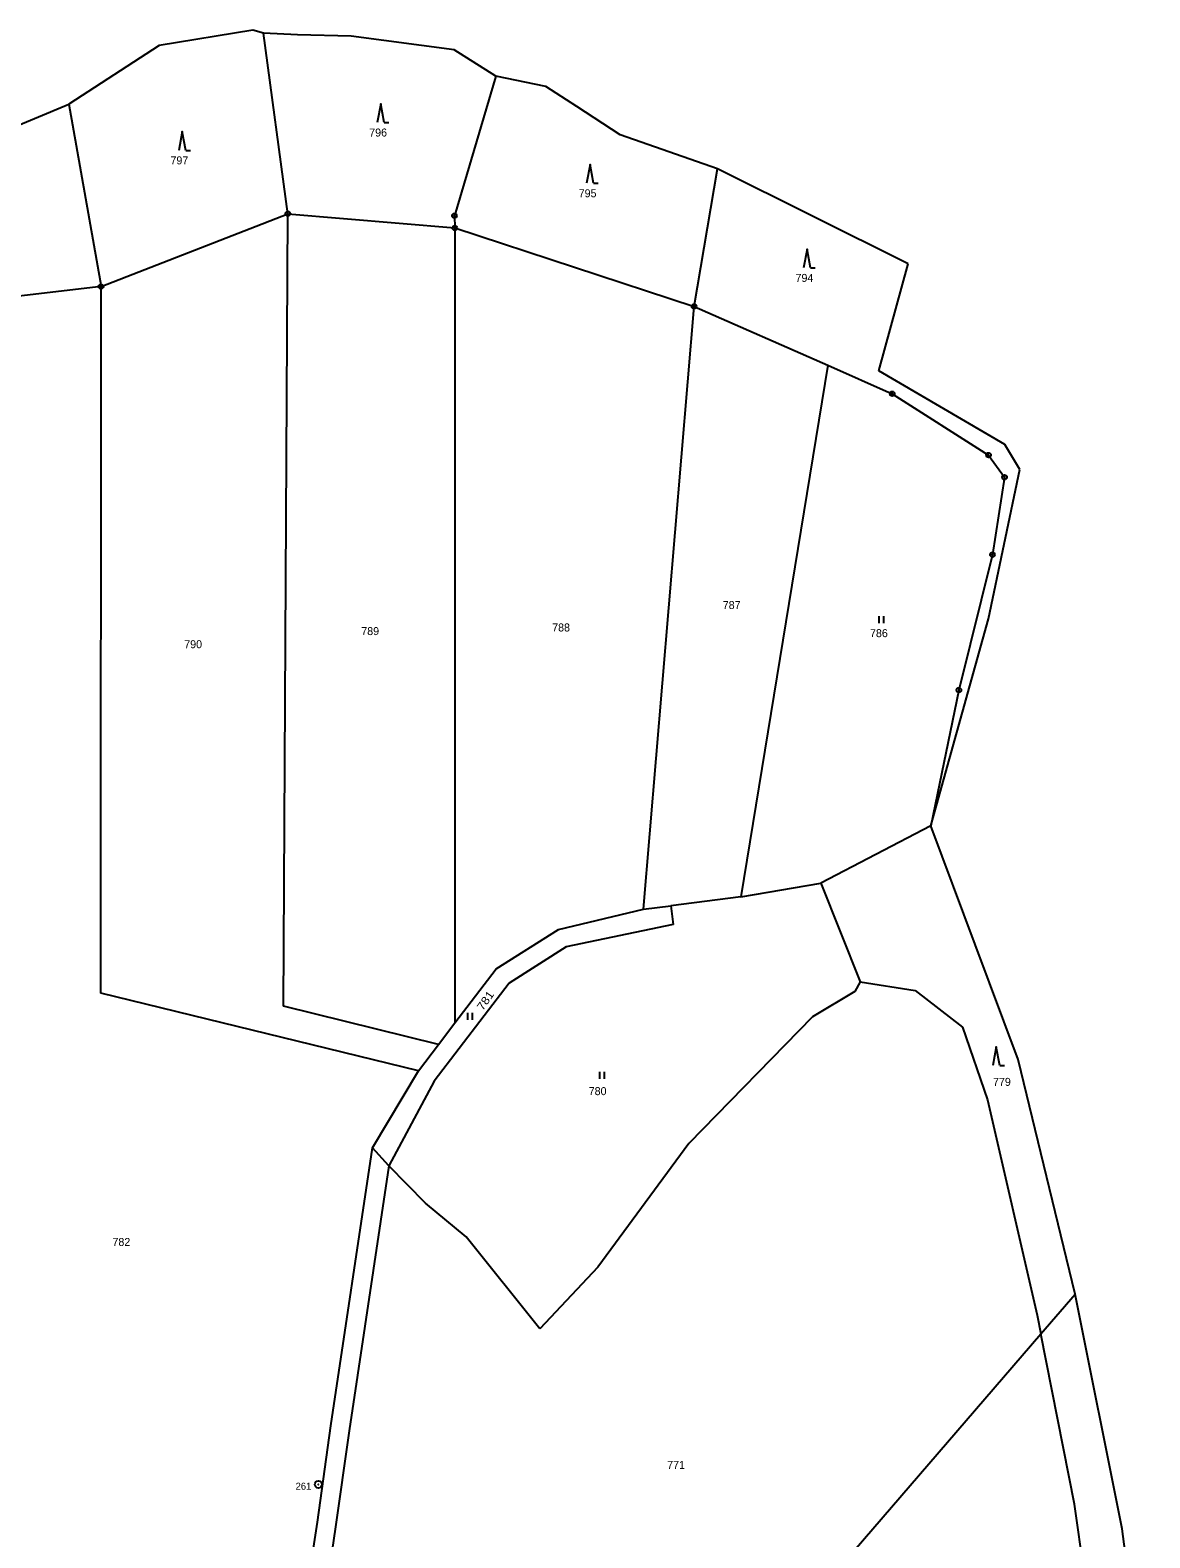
# Model space of a CAD drawing. Extents: x -719614 to -717765, y -1095834 to -1093862.
# Drawn here: x -719008.1 to -718769.8, y -1094182.4 to -1093861.5 of the extents above; entities that cross this region are included whole.
import ezdxf
from ezdxf.enums import TextEntityAlignment as Align

# ---------------------------------------------------------------- set-up
doc = ezdxf.new("R2010")
doc.units = 0
doc.header["$LTSCALE"] = 0.68
for name, color, linetype, lineweight in [('1', 7, 'Continuous', 25), ('3', 7, 'Continuous', 25), ('8', 7, 'Continuous', 25)]:
    doc.layers.add(name, color=color, linetype=linetype, lineweight=lineweight)
doc.layers.add('2', color=7, linetype='Continuous')

msp = doc.modelspace()

# ---------------------------------------------------------------- linework, layer by layer
at = {"layer": '1'}
for p, q in [((-718960.69, -1093861.54), (-718980.62, -1093864.8)), ((-718958.46, -1093862.15), (-718960.69, -1093861.54)), ((-718953.27, -1093900.59), (-718958.46, -1093862.15)), ((-718917.86, -1093865.71), (-718939.76, -1093862.79)), ((-718980.62, -1093864.8), (-718999.88, -1093877.31)), ((-718909.01, -1093871.3), (-718917.86, -1093865.71)), ((-718909.01, -1093871.3), (-718917.82, -1093901.03)), ((-718898.35, -1093873.52), (-718909.01, -1093871.3)), ((-718891.76, -1093877.82), (-718898.35, -1093873.52)), ((-719037.22, -1093892.85), (-718999.88, -1093877.31)), ((-718999.88, -1093877.31), (-718993.03, -1093916.09)), ((-718882.56, -1093883.81), (-718891.76, -1093877.82)), ((-718861.84, -1093891.05), (-718882.56, -1093883.81)), ((-718866.79, -1093920.33), (-718861.84, -1093891.05)), ((-718821.26, -1093911.24), (-718861.84, -1093891.05)), ((-718993.03, -1093916.09), (-718953.27, -1093900.59)), ((-718954.22, -1094069.22), (-718953.27, -1093900.59)), ((-718953.27, -1093900.59), (-718917.75, -1093903.63)), ((-718917.82, -1093901.03), (-718917.75, -1093903.63)), ((-718917.75, -1093903.63), (-718866.79, -1093920.33)), ((-718917.75, -1093903.63), (-718917.69, -1094072.79)), ((-718827.51, -1093934.04), (-718821.26, -1093911.24)), ((-718993.03, -1093916.09), (-719018.35, -1093919.09)), ((-718993.07, -1094066.46), (-718993.03, -1093916.09)), ((-718877.59, -1094048.57), (-718866.79, -1093920.33)), ((-718866.79, -1093920.33), (-718838.35, -1093932.85)), ((-718838.35, -1093932.85), (-718856.82, -1094045.98)), ((-718838.35, -1093932.85), (-718824.61, -1093938.9)), ((-718800.69, -1093949.7), (-718827.51, -1093934.04)), ((-718824.61, -1093938.9), (-718804.13, -1093951.95)), ((-718797.47, -1093955.06), (-718800.69, -1093949.7)), ((-718804.13, -1093951.95), (-718800.71, -1093956.67)), ((-718804.11, -1093986.83), (-718797.47, -1093955.06)), ((-718800.71, -1093956.67), (-718803.31, -1093973.14)), ((-718803.31, -1093973.14), (-718810.43, -1094001.98)), ((-718816.38, -1094030.86), (-718804.11, -1093986.83)), ((-718810.43, -1094001.98), (-718816.38, -1094030.86)), ((-718816.38, -1094030.86), (-718839.82, -1094043.07)), ((-718806.97, -1094056.07), (-718816.38, -1094030.86)), ((-718856.82, -1094045.98), (-718839.82, -1094043.07)), ((-718839.82, -1094043.07), (-718831.45, -1094064.06)), ((-718856.82, -1094045.98), (-718871.76, -1094047.85)), ((-718895.62, -1094052.88), (-718877.59, -1094048.57)), ((-718877.59, -1094048.57), (-718871.76, -1094047.85)), ((-718871.76, -1094047.85), (-718871.27, -1094051.82)), ((-718908.92, -1094061.31), (-718895.62, -1094052.88)), ((-718871.27, -1094051.82), (-718894.04, -1094056.62)), ((-718797.81, -1094080.58), (-718806.97, -1094056.07)), ((-718894.04, -1094056.62), (-718906.17, -1094064.31)), ((-718917.69, -1094072.79), (-718908.92, -1094061.31)), ((-718906.17, -1094064.31), (-718922.12, -1094085.2)), ((-718831.45, -1094064.06), (-718832.58, -1094066.09)), ((-718831.45, -1094064.06), (-718819.77, -1094065.89)), ((-718925.44, -1094082.95), (-718993.07, -1094066.46)), ((-718832.58, -1094066.09), (-718841.56, -1094071.51)), ((-718819.77, -1094065.89), (-718809.68, -1094073.66)), ((-718921.18, -1094077.36), (-718954.22, -1094069.22)), ((-718841.56, -1094071.51), (-718867.89, -1094098.42)), ((-718921.18, -1094077.36), (-718917.69, -1094072.79)), ((-718809.68, -1094073.66), (-718804.32, -1094089.18)), ((-718925.44, -1094082.95), (-718921.18, -1094077.36)), ((-718785.72, -1094130.53), (-718797.81, -1094080.58)), ((-718935.27, -1094099.37), (-718925.44, -1094082.95)), ((-718922.12, -1094085.2), (-718931.79, -1094103.17)), ((-718804.32, -1094089.18), (-718793.76, -1094134.99)), ((-718944.11, -1094158.53), (-718935.27, -1094099.37)), ((-718931.79, -1094103.17), (-718935.27, -1094099.37)), ((-718867.89, -1094098.42), (-718887.31, -1094124.74)), ((-718931.79, -1094103.17), (-718940.22, -1094159.58)), ((-718923.94, -1094111.13), (-718931.79, -1094103.17)), ((-718915.29, -1094118.33), (-718923.94, -1094111.13)), ((-718899.61, -1094137.91), (-718915.29, -1094118.33)), ((-718887.31, -1094124.74), (-718899.61, -1094137.91)), ((-718792.98, -1094138.94), (-718785.72, -1094130.53)), ((-718775.69, -1094180.41), (-718785.72, -1094130.53)), ((-718793.76, -1094134.99), (-718792.98, -1094138.94)), ((-718901.4, -1094264.73), (-718792.98, -1094138.94)), ((-718785.85, -1094175.19), (-718792.98, -1094138.94)), ((-718946.98, -1094179.04), (-718944.11, -1094158.53)), ((-718940.22, -1094159.58), (-718943.16, -1094180.53)), ((-718780.62, -1094211.83), (-718785.85, -1094175.19)), ((-718949.83, -1094197.86), (-718946.98, -1094179.04)), ((-718943.16, -1094180.53), (-718945.93, -1094198.76)), ((-718769.79, -1094224), (-718775.69, -1094180.41))]:
    msp.add_line(p, q, dxfattribs=at)
msp.add_lwpolyline([(-718939.76, -1093862.79), (-718951.23, -1093862.57), (-718958.46, -1093862.15)], dxfattribs=at)
at = {"layer": '3'}
for p, q in [((-718932.74, -1093881.19), (-718931.744, -1093881.19)), ((-718975, -1093887.12), (-718974.004, -1093887.12)), ((-718888.19, -1093894.12), (-718887.194, -1093894.12)), ((-718842, -1093912.13), (-718841.004, -1093912.13)), ((-718827.431, -1093987.72), (-718827.431, -1093986.22)), ((-718826.43, -1093987.72), (-718826.43, -1093986.22)), ((-718914.941, -1094072.16), (-718914.941, -1094070.66)), ((-718913.94, -1094072.16), (-718913.94, -1094070.66)), ((-718886.891, -1094084.66), (-718886.891, -1094083.16)), ((-718885.89, -1094084.66), (-718885.89, -1094083.16)), ((-718801.74, -1094081.88), (-718800.744, -1094081.88))]:
    msp.add_line(p, q, dxfattribs=at)
for points in [[(-718932.74, -1093881.19), (-718933.49, -1093877.19), (-718934.24, -1093881.19)], [(-718975, -1093887.12), (-718975.75, -1093883.12), (-718976.5, -1093887.12)], [(-718888.19, -1093894.12), (-718888.94, -1093890.12), (-718889.69, -1093894.12)], [(-718842, -1093912.13), (-718842.75, -1093908.13), (-718843.5, -1093912.13)], [(-718801.74, -1094081.88), (-718802.49, -1094077.88), (-718803.24, -1094081.88)]]:
    msp.add_lwpolyline(points, dxfattribs=at)
at = {"layer": '8'}
for centre, radius in [((-718953.27, -1093900.5899), 0.5), ((-718953.27, -1093900.5899), 0.0303), ((-718917.82, -1093901.0299), 0.5), ((-718917.82, -1093901.0299), 0.0303), ((-718917.75, -1093903.6299), 0.5), ((-718917.75, -1093903.6299), 0.0303), ((-718993.03, -1093916.0899), 0.5), ((-718993.03, -1093916.0899), 0.0303), ((-718866.79, -1093920.3299), 0.5), ((-718866.79, -1093920.3299), 0.0303), ((-718824.61, -1093938.8999), 0.5), ((-718824.61, -1093938.8999), 0.0303), ((-718804.13, -1093951.9499), 0.5), ((-718804.13, -1093951.9499), 0.0303), ((-718800.71, -1093956.6699), 0.5), ((-718800.71, -1093956.6699), 0.0303), ((-718803.31, -1093973.1399), 0.5), ((-718803.31, -1093973.1399), 0.0303), ((-718810.43, -1094001.9799), 0.5), ((-718810.43, -1094001.9799), 0.0303), ((-718946.77, -1094170.9998), 0.75), ((-718946.77, -1094170.9998), 0.03)]:
    msp.add_circle(centre, radius, dxfattribs=at)

# ---------------------------------------------------------------- texts
at = {"layer": '2'}
for s, p in [('796', (-718934.049, -1093884.172)), ('797', (-718976.349, -1093890.102)), ('795', (-718889.459, -1093897.102)), ('794', (-718843.309, -1093915.112)), ('787', (-718858.799, -1093984.722)), ('789', (-718935.739, -1093990.262)), ('788', (-718895.109, -1093989.492)), ('790', (-718973.419, -1093993.052)), ('786', (-718827.459, -1093990.702)), ('779', (-718801.279, -1094086.182)), ('780', (-718887.329, -1094088.152)), ('782', (-718988.699, -1094120.242)), ('771', (-718870.629, -1094167.692))]:
    msp.add_text(s, height=1.7, dxfattribs=at).set_placement(p, align=Align.CENTER)
at = {"layer": '2', "width": 1.15}
msp.add_text('781', height=1.7, rotation=55, dxfattribs=at).set_placement((-718910.5144, -1094068.5065), align=Align.CENTER)
at = {"layer": '8'}
msp.add_text('261', height=1.5, dxfattribs=at).set_placement((-718948.269, -1094172.117), align=Align.RIGHT)

doc.saveas('drawing.dxf')
